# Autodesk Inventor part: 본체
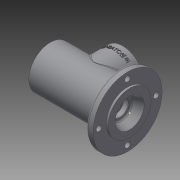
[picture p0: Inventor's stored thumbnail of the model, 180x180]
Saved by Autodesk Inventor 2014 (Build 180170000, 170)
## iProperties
Created: 2016-08
Part Number: 본체
Material: 일반
Document SubType Name: Modeling
Designer: USER
Density: 1 g/cm^3
Appearance: 기본값
Author: USER
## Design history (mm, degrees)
sketch "스케치1"
  geometry: 1 further point
sketch "스케치2"
  geometry: L1 (-16.69, 0)-(0, 0); L2 (-115, 0)-(-115, 31); L3 (-115, 31)-(-13, 31); L4 (-13, 31)-(-13, 50); L5 (-13, 50)-(-3, 50); L6 (-3, 50)-(-3, 31); L7 (-3, 31)-(0, 31); L8 (0, 31)-(0, 0); L9 (0, 0)-(-115, 0)
  constraints: 18 end point, 4 parallel, 2 collinear, 2 perpendicular, 1 horizontal, 1 point on line
  dimensions: "d5" = 62 diameter of L3 L1; "d6" = 100 diameter of L5 L1; "d7" = 62 diameter of L7 L1; "d8" = 115 distance between parallel lines of L8 L2; "d9" = 102 distance of L2.end L3.end; "d10" = 10 distance of L4.end L5.end
revolve "회전1" sketch "스케치2" stored, may be unused: angle "d11" = 90 deg
node "작업 평면1"
sketch "스케치3"
  geometry: L1 (115, 31)-(115, -31) reference; C1 r 30 at (59, 0); 1 further point
  constraints: 1 centre point, 1 horizontal alignment
  dimensions: "d13" = 60 diameter of C1; "d14" = 56 distance from line of L1 C1.centre
extrude "돌출1" join sketch "스케치3" stored distance "d15" = 10; taper "d16" = 0 deg
sketch "스케치4" dims "d17" = 48
  geometry: C1 r 30 at (0, 0) reference; 3 further points
  constraints: 2 vertical alignment, 1 coincident, 2 other
hole "구멍1" sketch "스케치4" at (0, 24) diameter "d18" = 3.242; stored, may be unused: countersink angle "d22" = 90 deg, drill point angle "d24" = 118 deg; dims "d19" = 8, "d20" = 4, "d21" = 2, "d23" = 10
sketch "스케치7"
  geometry: C1 r 31 at (0, 0) reference; C2 r 21 at (0, 0)
  constraints: 1 centre point, 1 coincident
  dimensions: "d28" = 42 diameter of C2
extrude "돌출2" cut sketch "스케치7" distance "d29" = 9; taper "d30" = 0 deg
sketch "스케치9"
  geometry: C1 r 21 at (0, 0) reference; C2 r 24 at (0, 0)
  constraints: 1 centre point, 1 coincident
  dimensions: "d32" = 48 diameter of C2
extrude "돌출3" cut sketch "스케치9" distance "d33" = 3; taper "d34" = 0 deg
sketch "스케치10"
  geometry: C1 r 24 at (0, 0) reference; C2 r 20 at (0, 0)
  constraints: 1 centre point, 1 coincident
  dimensions: "d35" = 40 diameter of C2
extrude "돌출4" cut sketch "스케치10" distance "d36" = 9; taper "d37" = 0 deg
feature "스레드1" dims "d62" = 10, "d63" = 0
chamfer "모따기1" distance "d64" = 1; stored, may be unused: second distance "d65" = 2, angle "d66" = 45 deg
fillet "모깎기4" dims "d79" = 3
fillet "모깎기5" dims "d83" = 3
sketch "스케치22" dims "d84" = 83
  geometry: C1 r 50 at (0, 0) reference; C2 r 31 at (0, 0) reference; C3 r 4 at (0, 41.5); 1 further point
  constraints: 2 vertical alignment, 1 centre point, 1 coincident, 2 other
  dimensions: "d85" = 8 diameter of C3
extrude "돌출13" cut sketch "스케치22" distance "d86" = 16.55; taper "d87" = 0 deg
node "작업 평면2"
sketch "스케치24"
  geometry: L1 (-56, -80)-(-56, -18) reference; L2 (-30, 0)-(30, 0) reference; 2 further points
  constraints: 1 other
  dimensions: "d91" = 56 distance from line of point (0, -10) L1; "d92" = 10 distance from line of point (0, -10) L2
feature "엠보싱1" sketch "스케치24" dims "d93" = 0.5, "d94" = 0
sketch "스케치28"
  geometry: C1 r 20 at (0, 0) reference; C2 r 17.5 at (0, 0)
  constraints: 1 centre point, 1 coincident
  dimensions: "d95" = 35 diameter of C2
extrude "돌출14" cut sketch "스케치28" distance "d96" = 3.25; taper "d97" = 0 deg
sketch "스케치29"
  geometry: C1 r 17.5 at (0, 0) reference; C2 r 18.5 at (0, 0)
  constraints: 1 centre point, 1 coincident
  dimensions: "d98" = 37 diameter of C2
extrude "돌출15" cut sketch "스케치29" distance "d99" = 1.75; taper "d100" = 0 deg
sketch "스케치30"
  geometry: C1 r 18.5 at (0, 0) reference; C2 r 17.5 at (0, 0)
  constraints: 1 centre point, 1 coincident
  dimensions: "d101" = 35 diameter of C2
extrude "돌출16" cut sketch "스케치30" distance "d102" = 11; taper "d103" = 0 deg
sketch "스케치31"
  geometry: C1 r 17.5 at (0, 0) reference; C2 r 26 at (0, 0)
  constraints: 1 centre point, 1 coincident
  dimensions: "d104" = 52 diameter of C2
extrude "돌출17" cut sketch "스케치31" distance "d105" = 38; taper "d106" = 0 deg
sketch "스케치32"
  geometry: C1 r 17.5 at (0, 0); 2 further points
  constraints: 1 centre point, 1 coincident, 1 horizontal alignment
  dimensions: "d107" = 35 diameter of C1
extrude "돌출18" cut sketch "스케치32" distance "d108" = 11; taper "d109" = 0 deg
sketch "스케치33"
  geometry: C1 r 17.5 at (0, 0) reference; C2 r 16.5 at (0, 0)
  constraints: 1 centre point, 1 coincident
  dimensions: "d110" = 33 diameter of C2
extrude "돌출19" cut sketch "스케치33" distance "d111" = 5; taper "d112" = 0 deg
sketch "스케치34"
  geometry: C1 r 16.5 at (0, 0) reference; C2 r 10 at (0, 0)
  constraints: 1 centre point, 1 coincident
  dimensions: "d113" = 20 diameter of C2
extrude "돌출20" cut sketch "스케치34" distance "d114" = 2.7; taper "d115" = 0 deg
sketch "스케치35"
  geometry: C1 r 10 at (0, 0) reference; C2 r 12.5 at (0, 0)
  constraints: 1 centre point, 1 coincident
  dimensions: "d116" = 25 diameter of C2
extrude "돌출21" cut sketch "스케치35" distance "d117" = 7.3; taper "d118" = 0 deg
sketch "스케치37"
  geometry: L1 (-14, -12.5)-(-14, 12.5) reference; L2 (0, -31)-(0, 31) reference; L3 (-14, 0)-(-14, 16); L4 (-14, 16)-(0, 21); L5 (0, 21)-(0, 0); L6 (0, 0)-(-14, 0)
  constraints: 8 end point, 2 point on line, 1 collinear, 1 midpoint, 1 perpendicular
  dimensions: "d119" = 16 distance of L3.start L3.end; "d120" = 21 distance of L5.end L4.end
revolve "회전3" sketch "스케치37" stored, may be unused: angle "d121" = 90 deg
chamfer "모따기5" distance "d122" = 1; stored, may be unused: second distance "d123" = 2, angle "d124" = 30 deg
fillet "모깎기6" dims "d125" = 3
fillet "모깎기7" dims "d126" = 0.3
fillet "모깎기8" dims "d127" = 3
fillet "모깎기9" dims "d128" = 0.3
fillet "모깎기10" dims "d129" = 3
chamfer "모따기6" distance "d130" = 0.7; stored, may be unused: second distance "d131" = 2, angle "d132" = 30 deg
sketch "스케치40"
  geometry: C1 r 30 at (0, 0) reference; C2 r 19 at (0, 0); 1 further point
  constraints: 1 centre point, 1 coincident
  dimensions: "d134" = 38 diameter of C2
extrude "돌출22" cut sketch "스케치40" stored distance "d135" = 7.3; taper "d136" = 0 deg
sketch "스케치41"
  geometry: 1 further point
node "솔리드1"
pattern_circular "원형 패턴1" dims angle "d26" = 360 deg
pattern_circular "원형 패턴2" dims angle "d89" = 360 deg
other parameters: "d12" = 49
